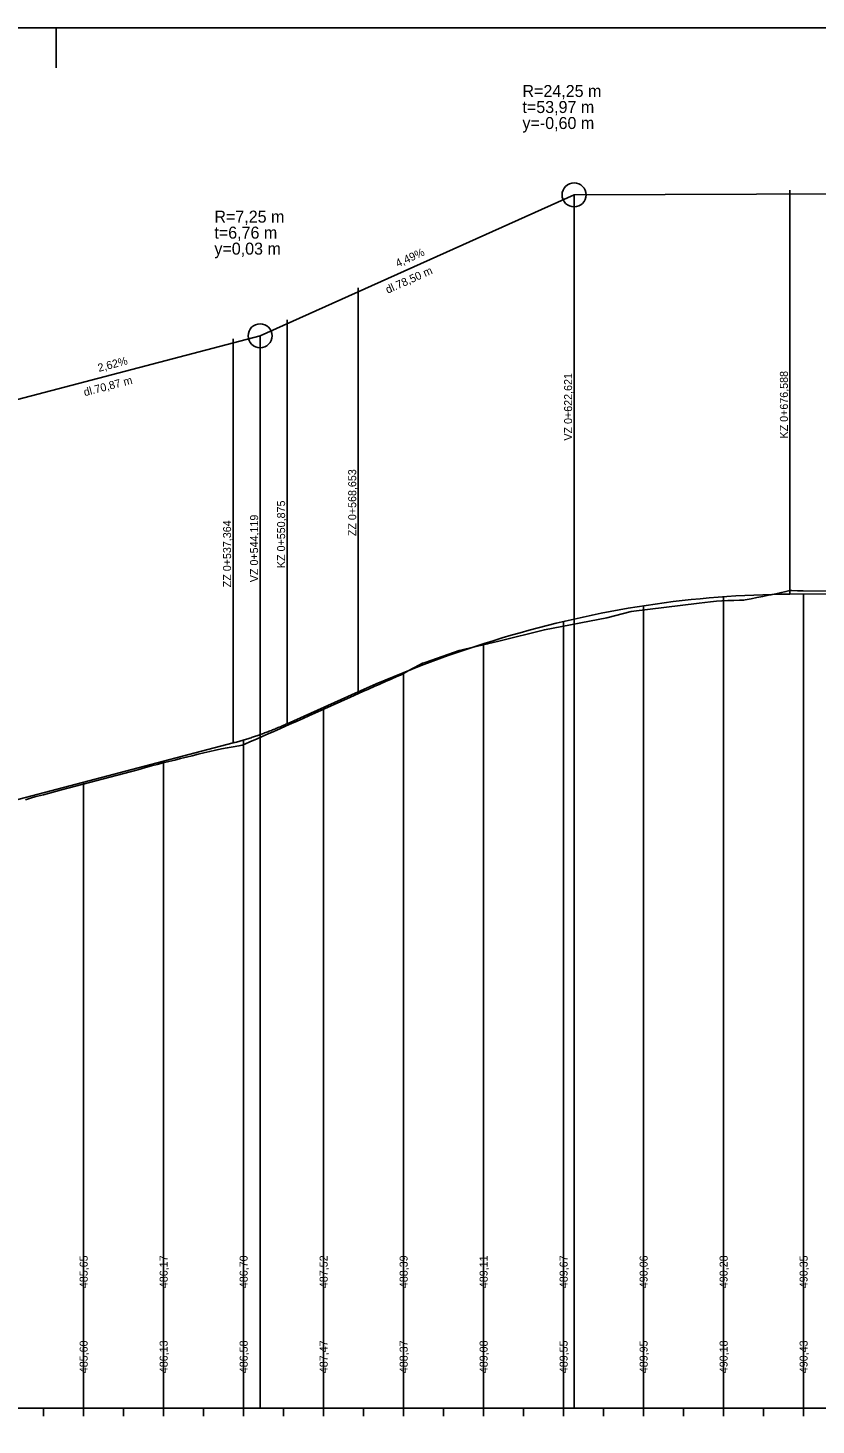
# Model space of a CAD drawing. Extents: x -632716 to -629545, y -1094726 to -1088285.
# Drawn here: x -631997.4 to -631800.3, y -1091019.4 to -1090670.2 of the extents above; entities that cross this region are included whole.
import ezdxf

# ---------------------------------------------------------------- set-up
doc = ezdxf.new("R2010")
doc.units = 0
for name, color, linetype in [('20', 7, 'Continuous'), ('Default', 7, 'Continuous'), ('formát', 7, 'Continuous'), ('NIVELETA_VYSKY', 7, 'Continuous'), ('REZ_TENKA', 7, 'Continuous'), ('REZ_TLUSTA', 7, 'Continuous'), ('SKLONY_NIVELETA', 7, 'Continuous'), ('SKLONY_POPIS', 7, 'Continuous'), ('TECNY_NIVELETA', 7, 'Continuous'), ('TEREN_VYSKY', 7, 'Continuous'), ('VOZOVKA', 7, 'Continuous')]:
    doc.layers.add(name, color=color, linetype=linetype)

msp = doc.modelspace()

# ---------------------------------------------------------------- linework, layer by layer
at = {"layer": '20'}
for points in [[(-631803.46, -1090811.73), (-631803.46, -1090965.2), (-631803.46, -1091015.2), (-631803.46, -1090955.2)], [(-631843.46, -1090814.63), (-631843.46, -1090965.2), (-631843.46, -1091015.2), (-631843.46, -1090955.2)], [(-631823.46, -1090812.36), (-631823.46, -1090965.2), (-631823.46, -1091015.2), (-631823.46, -1090955.2)], [(-631863.46, -1090818.54), (-631863.46, -1090965.2), (-631863.46, -1091015.2), (-631863.46, -1090955.2)], [(-631883.46, -1090824.11), (-631883.46, -1090965.2), (-631883.46, -1091015.2), (-631883.46, -1090955.2)], [(-631903.46, -1090831.32), (-631903.46, -1090965.2), (-631903.46, -1091015.2), (-631903.46, -1090955.2)], [(-631923.46, -1090840.03), (-631923.46, -1090965.2), (-631923.46, -1091015.2), (-631923.46, -1090955.2)], [(-631943.46, -1090848.19), (-631943.46, -1090965.2), (-631943.46, -1091015.2), (-631943.46, -1090955.2)], [(-631963.46, -1090853.48), (-631963.46, -1090965.2), (-631963.46, -1091015.2), (-631963.46, -1090955.2)], [(-631983.46, -1090858.73), (-631983.46, -1090965.2), (-631983.46, -1091015.2), (-631983.46, -1090955.2)]]:
    msp.add_lwpolyline(points, dxfattribs=at)
at = {"layer": 'Default'}
for p, q in [((-631806.88, -1090811.74), (-631634.2, -1090811.12)), ((-631806.88, -1090811.74), (-631634.2, -1090811.12)), ((-631932.59, -1090844.12), (-631914.81, -1090836.15)), ((-631932.59, -1090844.12), (-631914.81, -1090836.15)), ((-632004.44, -1090864.23), (-631946.1, -1090848.93)), ((-632004.44, -1090864.23), (-631946.1, -1090848.93))]:
    msp.add_line(p, q, dxfattribs=at)
for points in [[(-631914.81, -1090836.15), (-631912.56, -1090835.15), (-631910.31, -1090834.17), (-631908.06, -1090833.21), (-631905.82, -1090832.28), (-631903.57, -1090831.36), (-631901.32, -1090830.47), (-631899.07, -1090829.59), (-631896.82, -1090828.74), (-631894.57, -1090827.91), (-631892.32, -1090827.1), (-631890.08, -1090826.31), (-631887.83, -1090825.54), (-631885.58, -1090824.79), (-631883.33, -1090824.06), (-631881.08, -1090823.36), (-631878.83, -1090822.67), (-631876.58, -1090822.01), (-631874.33, -1090821.36), (-631872.09, -1090820.74), (-631869.84, -1090820.14), (-631867.59, -1090819.56), (-631865.34, -1090818.99), (-631863.09, -1090818.46), (-631858.59, -1090817.44), (-631856.35, -1090816.96), (-631854.1, -1090816.5), (-631851.85, -1090816.07), (-631849.6, -1090815.65), (-631847.35, -1090815.26), (-631845.1, -1090814.89), (-631842.85, -1090814.54), (-631840.61, -1090814.2), (-631838.36, -1090813.89), (-631836.11, -1090813.6), (-631833.86, -1090813.34), (-631831.61, -1090813.09), (-631829.36, -1090812.86), (-631827.11, -1090812.65), (-631824.86, -1090812.47), (-631822.62, -1090812.3), (-631820.37, -1090812.16), (-631818.12, -1090812.04), (-631815.87, -1090811.94), (-631813.62, -1090811.86), (-631811.37, -1090811.8), (-631809.12, -1090811.76), (-631806.88, -1090811.74)], [(-631914.81, -1090836.15), (-631912.56, -1090835.15), (-631910.31, -1090834.17), (-631908.06, -1090833.21), (-631905.82, -1090832.28), (-631903.57, -1090831.36), (-631901.32, -1090830.47), (-631899.07, -1090829.59), (-631896.82, -1090828.74), (-631894.57, -1090827.91), (-631892.32, -1090827.1), (-631890.08, -1090826.31), (-631887.83, -1090825.54), (-631885.58, -1090824.79), (-631883.33, -1090824.06), (-631881.08, -1090823.36), (-631878.83, -1090822.67), (-631876.58, -1090822.01), (-631874.33, -1090821.36), (-631872.09, -1090820.74), (-631869.84, -1090820.14), (-631867.59, -1090819.56), (-631865.34, -1090818.99), (-631863.09, -1090818.46), (-631858.59, -1090817.44), (-631856.35, -1090816.96), (-631854.1, -1090816.5), (-631851.85, -1090816.07), (-631849.6, -1090815.65), (-631847.35, -1090815.26), (-631845.1, -1090814.89), (-631842.85, -1090814.54), (-631840.61, -1090814.2), (-631838.36, -1090813.89), (-631836.11, -1090813.6), (-631833.86, -1090813.34), (-631831.61, -1090813.09), (-631829.36, -1090812.86), (-631827.11, -1090812.65), (-631824.86, -1090812.47), (-631822.62, -1090812.3), (-631820.37, -1090812.16), (-631818.12, -1090812.04), (-631815.87, -1090811.94), (-631813.62, -1090811.86), (-631811.37, -1090811.8), (-631809.12, -1090811.76), (-631806.88, -1090811.74)], [(-631946.1, -1090848.93), (-631945.82, -1090848.85), (-631945.54, -1090848.78), (-631945.26, -1090848.7), (-631944.97, -1090848.62), (-631944.69, -1090848.54), (-631944.41, -1090848.46), (-631944.13, -1090848.38), (-631943.85, -1090848.3), (-631943.57, -1090848.22), (-631943.29, -1090848.13), (-631943, -1090848.05), (-631942.72, -1090847.96), (-631942.44, -1090847.87), (-631942.16, -1090847.79), (-631941.88, -1090847.7), (-631941.6, -1090847.61), (-631941.32, -1090847.51), (-631941.03, -1090847.42), (-631940.75, -1090847.33), (-631940.47, -1090847.23), (-631940.19, -1090847.13), (-631939.91, -1090847.04), (-631939.63, -1090846.94), (-631939.06, -1090846.74), (-631938.78, -1090846.64), (-631938.5, -1090846.53), (-631938.22, -1090846.43), (-631937.94, -1090846.33), (-631937.66, -1090846.22), (-631937.37, -1090846.11), (-631937.09, -1090846), (-631936.81, -1090845.89), (-631936.53, -1090845.78), (-631936.25, -1090845.67), (-631935.97, -1090845.56), (-631935.69, -1090845.45), (-631935.4, -1090845.33), (-631935.12, -1090845.22), (-631934.84, -1090845.1), (-631934.56, -1090844.98), (-631934.28, -1090844.86), (-631934, -1090844.74), (-631933.71, -1090844.62), (-631933.43, -1090844.5), (-631933.15, -1090844.37), (-631932.87, -1090844.25), (-631932.59, -1090844.12)], [(-631946.1, -1090848.93), (-631945.82, -1090848.85), (-631945.54, -1090848.78), (-631945.26, -1090848.7), (-631944.97, -1090848.62), (-631944.69, -1090848.54), (-631944.41, -1090848.46), (-631944.13, -1090848.38), (-631943.85, -1090848.3), (-631943.57, -1090848.22), (-631943.29, -1090848.13), (-631943, -1090848.05), (-631942.72, -1090847.96), (-631942.44, -1090847.87), (-631942.16, -1090847.79), (-631941.88, -1090847.7), (-631941.6, -1090847.61), (-631941.32, -1090847.51), (-631941.03, -1090847.42), (-631940.75, -1090847.33), (-631940.47, -1090847.23), (-631940.19, -1090847.13), (-631939.91, -1090847.04), (-631939.63, -1090846.94), (-631939.06, -1090846.74), (-631938.78, -1090846.64), (-631938.5, -1090846.53), (-631938.22, -1090846.43), (-631937.94, -1090846.33), (-631937.66, -1090846.22), (-631937.37, -1090846.11), (-631937.09, -1090846), (-631936.81, -1090845.89), (-631936.53, -1090845.78), (-631936.25, -1090845.67), (-631935.97, -1090845.56), (-631935.69, -1090845.45), (-631935.4, -1090845.33), (-631935.12, -1090845.22), (-631934.84, -1090845.1), (-631934.56, -1090844.98), (-631934.28, -1090844.86), (-631934, -1090844.74), (-631933.71, -1090844.62), (-631933.43, -1090844.5), (-631933.15, -1090844.37), (-631932.87, -1090844.25), (-631932.59, -1090844.12)]]:
    msp.add_lwpolyline(points, dxfattribs=at)
at = {"layer": 'formát'}
msp.add_line((-631990.3, -1090680.2), (-631990.3, -1090670.2), dxfattribs=at)
msp.add_lwpolyline([(-632585.29, -1091264.2), (-630730.3, -1091264.2), (-630730.3, -1090670.2), (-632585.29, -1090670.2)], close=True, dxfattribs=at)
at = {"layer": 'REZ_TENKA'}
for p, q in [((-631993.46, -1091017.2), (-631993.46, -1091015.2)), ((-631973.46, -1091017.2), (-631973.46, -1091015.2)), ((-631963.46, -1091017.2), (-631963.46, -1091015.2)), ((-631953.46, -1091017.2), (-631953.46, -1091015.2)), ((-631943.46, -1091017.2), (-631943.46, -1091015.2)), ((-631933.46, -1091017.2), (-631933.46, -1091015.2)), ((-631923.46, -1091017.2), (-631923.46, -1091015.2)), ((-631913.46, -1091017.2), (-631913.46, -1091015.2)), ((-631903.46, -1091017.2), (-631903.46, -1091015.2)), ((-631893.46, -1091017.2), (-631893.46, -1091015.2)), ((-631873.46, -1091017.2), (-631873.46, -1091015.2)), ((-631863.46, -1091017.2), (-631863.46, -1091015.2)), ((-631853.46, -1091017.2), (-631853.46, -1091015.2)), ((-631843.46, -1091017.2), (-631843.46, -1091015.2)), ((-631833.46, -1091017.2), (-631833.46, -1091015.2)), ((-631823.46, -1091017.2), (-631823.46, -1091015.2)), ((-631813.46, -1091017.2), (-631813.46, -1091015.2)), ((-631803.46, -1091017.2), (-631803.46, -1091015.2))]:
    msp.add_line(p, q, dxfattribs=at)
at = {"layer": 'REZ_TLUSTA'}
for p, q in [((-631983.46, -1091017.2), (-631983.46, -1091013.2)), ((-631883.46, -1091017.2), (-631883.46, -1091013.2)), ((-632483.46, -1091015.2), (-630763.46, -1091015.2))]:
    msp.add_line(p, q, dxfattribs=at)
at = {"layer": 'SKLONY_NIVELETA'}
for p, q in [((-631939.34, -1090747.15), (-631860.84, -1090711.93)), ((-631860.84, -1090711.93), (-631618.66, -1090711.06)), ((-631860.84, -1090711.93), (-631860.84, -1091015.2)), ((-632010.21, -1090765.75), (-631939.34, -1090747.15)), ((-631939.34, -1090747.15), (-631939.34, -1091015.2)), ((-631806.88, -1090811.74), (-631634.2, -1090811.12)), ((-631932.59, -1090844.12), (-631914.81, -1090836.15)), ((-632004.44, -1090864.23), (-631946.1, -1090848.93))]:
    msp.add_line(p, q, dxfattribs=at)
for points in [[(-631914.81, -1090836.15), (-631912.56, -1090835.15), (-631910.31, -1090834.17), (-631908.06, -1090833.21), (-631905.82, -1090832.28), (-631903.57, -1090831.36), (-631901.32, -1090830.47), (-631899.07, -1090829.59), (-631896.82, -1090828.74), (-631894.57, -1090827.91), (-631892.32, -1090827.1), (-631890.08, -1090826.31), (-631887.83, -1090825.54), (-631885.58, -1090824.79), (-631883.33, -1090824.06), (-631881.08, -1090823.36), (-631878.83, -1090822.67), (-631876.58, -1090822.01), (-631874.33, -1090821.36), (-631872.09, -1090820.74), (-631869.84, -1090820.14), (-631867.59, -1090819.56), (-631865.34, -1090818.99), (-631863.09, -1090818.46), (-631858.59, -1090817.44), (-631856.35, -1090816.96), (-631854.1, -1090816.5), (-631851.85, -1090816.07), (-631849.6, -1090815.65), (-631847.35, -1090815.26), (-631845.1, -1090814.89), (-631842.85, -1090814.54), (-631840.61, -1090814.2), (-631838.36, -1090813.89), (-631836.11, -1090813.6), (-631833.86, -1090813.34), (-631831.61, -1090813.09), (-631829.36, -1090812.86), (-631827.11, -1090812.65), (-631824.86, -1090812.47), (-631822.62, -1090812.3), (-631820.37, -1090812.16), (-631818.12, -1090812.04), (-631815.87, -1090811.94), (-631813.62, -1090811.86), (-631811.37, -1090811.8), (-631809.12, -1090811.76), (-631806.88, -1090811.74)], [(-631946.1, -1090848.93), (-631945.82, -1090848.85), (-631945.54, -1090848.78), (-631945.26, -1090848.7), (-631944.97, -1090848.62), (-631944.69, -1090848.54), (-631944.41, -1090848.46), (-631944.13, -1090848.38), (-631943.85, -1090848.3), (-631943.57, -1090848.22), (-631943.29, -1090848.13), (-631943, -1090848.05), (-631942.72, -1090847.96), (-631942.44, -1090847.87), (-631942.16, -1090847.79), (-631941.88, -1090847.7), (-631941.6, -1090847.61), (-631941.32, -1090847.51), (-631941.03, -1090847.42), (-631940.75, -1090847.33), (-631940.47, -1090847.23), (-631940.19, -1090847.13), (-631939.91, -1090847.04), (-631939.63, -1090846.94), (-631939.06, -1090846.74), (-631938.78, -1090846.64), (-631938.5, -1090846.53), (-631938.22, -1090846.43), (-631937.94, -1090846.33), (-631937.66, -1090846.22), (-631937.37, -1090846.11), (-631937.09, -1090846), (-631936.81, -1090845.89), (-631936.53, -1090845.78), (-631936.25, -1090845.67), (-631935.97, -1090845.56), (-631935.69, -1090845.45), (-631935.4, -1090845.33), (-631935.12, -1090845.22), (-631934.84, -1090845.1), (-631934.56, -1090844.98), (-631934.28, -1090844.86), (-631934, -1090844.74), (-631933.71, -1090844.62), (-631933.43, -1090844.5), (-631933.15, -1090844.37), (-631932.87, -1090844.25), (-631932.59, -1090844.12)]]:
    msp.add_lwpolyline(points, dxfattribs=at)
for centre in [(-631860.84, -1090711.93), (-631939.34, -1090747.15)]:
    msp.add_circle(centre, 3, dxfattribs=at)
at = {"layer": 'TECNY_NIVELETA'}
for p, q in [((-631860.84, -1090711.93), (-631860.84, -1090711.93)), ((-631806.88, -1090811.74), (-631806.88, -1090710.74)), ((-631914.81, -1090836.15), (-631914.81, -1090735.15)), ((-631932.59, -1090844.12), (-631932.59, -1090743.12)), ((-631946.1, -1090848.93), (-631946.1, -1090747.93)), ((-631939.34, -1090747.15), (-631939.34, -1090747.15))]:
    msp.add_line(p, q, dxfattribs=at)
at = {"layer": 'VOZOVKA'}
msp.add_lwpolyline([(-631998.03, -1090863.11), (-631996.53, -1090862.68), (-631995.67, -1090862.43), (-631995.03, -1090862.26), (-631993.52, -1090861.86), (-631992.02, -1090861.46), (-631990.52, -1090861.06), (-631989.02, -1090860.66), (-631969.89, -1090855.6), (-631967.99, -1090855.04), (-631966.52, -1090854.66), (-631965.06, -1090854.29), (-631963.6, -1090853.92), (-631962.15, -1090853.55), (-631960.69, -1090853.19), (-631959.23, -1090852.82), (-631957.77, -1090852.46), (-631956.31, -1090852.11), (-631954.85, -1090851.75), (-631953.4, -1090851.4), (-631951.94, -1090851.05), (-631950.48, -1090850.71), (-631950.08, -1090850.61), (-631949.02, -1090850.43), (-631947.56, -1090850.17), (-631946.11, -1090849.91), (-631944.65, -1090849.65), (-631943.82, -1090849.5), (-631943.19, -1090849.23), (-631941.73, -1090848.59), (-631940.27, -1090847.96), (-631938.82, -1090847.32), (-631937.36, -1090846.67), (-631935.9, -1090846.03), (-631934.44, -1090845.38), (-631932.98, -1090844.74), (-631931.52, -1090844.09), (-631930.07, -1090843.44), (-631928.61, -1090842.79), (-631927.15, -1090842.13), (-631925.69, -1090841.48), (-631916.71, -1090837.44), (-631913.66, -1090836.09), (-631912.24, -1090835.46), (-631910.83, -1090834.83), (-631909.41, -1090834.21), (-631907.99, -1090833.59), (-631906.57, -1090832.97), (-631905.15, -1090832.35), (-631904.25, -1090831.96), (-631903.74, -1090831.69), (-631902.32, -1090830.92), (-631900.9, -1090830.16), (-631899.48, -1090829.41), (-631898.73, -1090829.01), (-631898.07, -1090828.78), (-631896.65, -1090828.3), (-631895.23, -1090827.81), (-631893.81, -1090827.32), (-631892.39, -1090826.82), (-631890.98, -1090826.32), (-631889.56, -1090825.81), (-631889.51, -1090825.79), (-631888.14, -1090825.48), (-631886.72, -1090825.16), (-631885.3, -1090824.82), (-631883.89, -1090824.49), (-631882.47, -1090824.15), (-631881.05, -1090823.8), (-631879.63, -1090823.45), (-631868.27, -1090820.62), (-631852.62, -1090817.67), (-631846.61, -1090816.03), (-631829.61, -1090814), (-631828.16, -1090813.83), (-631826.71, -1090813.67), (-631825.27, -1090813.5), (-631823.9, -1090813.36), (-631823.82, -1090813.36), (-631822.37, -1090813.32), (-631820.92, -1090813.28), (-631819.47, -1090813.25), (-631818.38, -1090813.23), (-631818.03, -1090813.16), (-631816.58, -1090812.87), (-631815.13, -1090812.58), (-631813.68, -1090812.3), (-631812.23, -1090812.02), (-631811.62, -1090811.91), (-631810.79, -1090811.72), (-631809.34, -1090811.39), (-631807.89, -1090811.07), (-631806.92, -1090810.85), (-631806.44, -1090810.85), (-631804.99, -1090810.86), (-631803.55, -1090810.88), (-631792.58, -1090810.98)], dxfattribs=at)

# ---------------------------------------------------------------- texts
at = {"layer": 'NIVELETA_VYSKY'}
for s, p in [('485,65', (-631982.46, -1090985.2)), ('486,17', (-631962.46, -1090985.2)), ('486,70', (-631942.46, -1090985.2)), ('487,52', (-631922.46, -1090985.2)), ('488,39', (-631902.46, -1090985.2)), ('489,11', (-631882.46, -1090985.2)), ('489,67', (-631862.46, -1090985.2)), ('490,06', (-631842.46, -1090985.2)), ('490,28', (-631822.46, -1090985.2)), ('490,35', (-631802.46, -1090985.2))]:
    msp.add_text(s, height=2, rotation=90, dxfattribs=at).set_placement(p)
at = {"layer": 'SKLONY_POPIS'}
for s, p in [('R=24,25 m', (-631873.75, -1090687.46)), ('t=53,97 m', (-631873.75, -1090691.46)), ('y=-0,60 m', (-631873.75, -1090695.46)), ('R=7,25 m', (-631950.77, -1090718.86)), ('t=6,76 m', (-631950.77, -1090722.86)), ('y=0,03 m', (-631950.77, -1090726.86))]:
    msp.add_text(s, height=3, dxfattribs=at).set_placement(p)
for s, rotation, p in [('4,49%', 24.1657, (-631904.94, -1090730.07)), ('dl.78,50 m', 24.1657, (-631907.42, -1090736.66)), ('2,62%', 14.7019, (-631979.64, -1090756.18)), ('dl.70,87 m', 14.7019, (-631983.17, -1090762.27)), ('VZ 0+622,621', 90, (-631861.34, -1090773.35)), ('KZ 0+676,588', 90, (-631807.38, -1090772.82)), ('ZZ 0+568,653', 90, (-631915.31, -1090797.23)), ('KZ 0+550,875', 90, (-631933.09, -1090805.21)), ('ZZ 0+537,364', 90, (-631946.6, -1090810.01)), ('VZ 0+544,119', 90, (-631939.84, -1090808.74))]:
    msp.add_text(s, height=2, rotation=rotation, dxfattribs=at).set_placement(p)
at = {"layer": 'TEREN_VYSKY'}
for s, p in [('485,60', (-631982.46, -1091006.46)), ('486,13', (-631962.46, -1091006.46)), ('486,58', (-631942.46, -1091006.46)), ('487,47', (-631922.46, -1091006.46)), ('488,37', (-631902.46, -1091006.46)), ('489,08', (-631882.46, -1091006.46)), ('489,55', (-631862.46, -1091006.46)), ('489,95', (-631842.46, -1091006.46)), ('490,18', (-631822.46, -1091006.46)), ('490,43', (-631802.46, -1091006.46))]:
    msp.add_text(s, height=2, rotation=90, dxfattribs=at).set_placement(p)

doc.saveas('drawing.dxf')
